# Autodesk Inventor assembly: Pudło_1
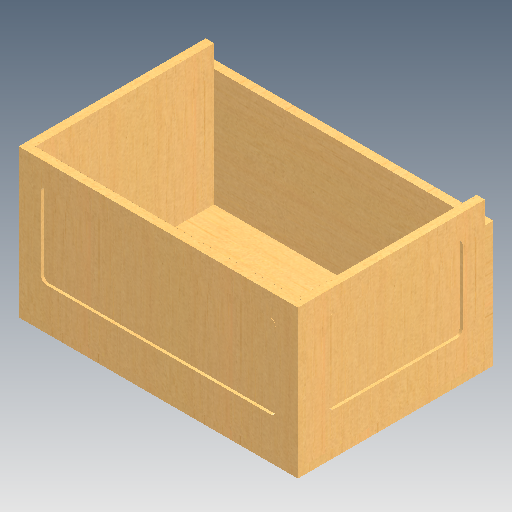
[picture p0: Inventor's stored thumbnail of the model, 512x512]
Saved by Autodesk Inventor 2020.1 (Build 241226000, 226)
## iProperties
Created: 2019-06
Part Number: Pudło_1
Document SubType Name: Assembly
Designer: F.Stasiak
Manager: www.cadconsulting.pl
Company: Fabian Stasiak CAD Consulting
Author: F.Stasiak
Subject: Zbiór ćwiczeń. Autodesk Inventor 2020. Kurs podstawowy
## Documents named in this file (5)
- C:\2020_Kurs_podstawowy\R6 Zespoły\Wiązania\Skrzynia I\Pudło_1.iam
- C:\2020_Kurs_podstawowy\R6 Zespoły\Wiązania\Skrzynia I\Spód.ipt
- C:\2020_Kurs_podstawowy\R6 Zespoły\Wiązania\Skrzynia I\Bok długi.ipt
- C:\2020_Kurs_podstawowy\R6 Zespoły\Wiązania\Skrzynia I\Bok krótki.ipt
- C:\2020_Kurs_podstawowy\R6 Zespoły\Wiązania\Skrzynia I\Bok niski_1.ipt
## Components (5 placed, 4 different names)
1. Spód:1
2. Bok długi:1
3. Bok krótki:1
4. Bok krótki:2
5. Bok niski:1
## Named parameters: d0_d7 = 0, d1_d8 = 0
